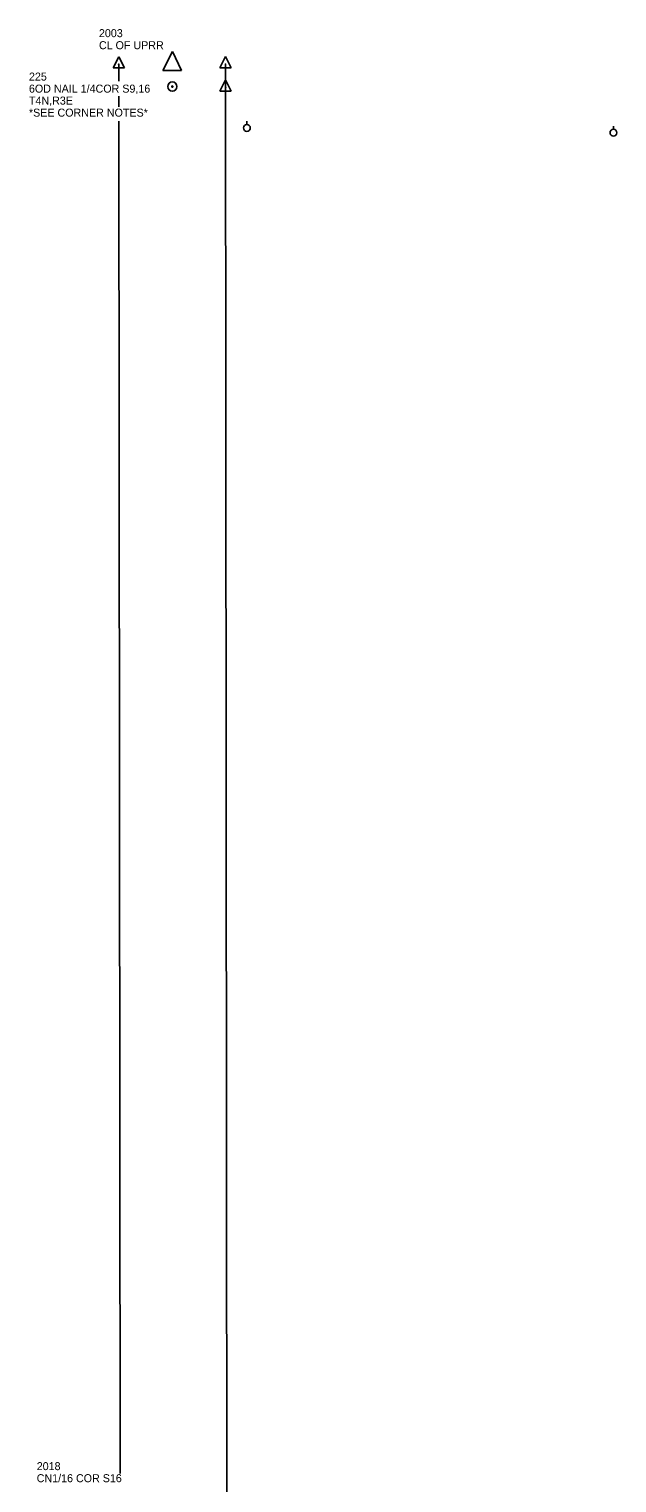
# Model space of a CAD drawing. Extents: x 1674300 to 1677561, y 225056 to 231852.
# Drawn here: x 1674554 to 1675105, y 230490 to 231852 of the extents above; entities that cross this region are included whole.
import ezdxf

# ---------------------------------------------------------------- set-up
doc = ezdxf.new("R2010")
doc.units = 0
for name, color, linetype in [('S_CAL_CORNER', 7, 'Continuous'), ('S_CAL_CORNER_ANNOT', 7, 'Continuous'), ('S_EXIST_ROW', 7, 'Continuous'), ('S_IRON_PIN', 7, 'Continuous'), ('S_IRON_PIN_ANNOT', 7, 'Continuous'), ('S_UTILITY_POLE', 7, 'Continuous')]:
    doc.layers.add(name, color=color, linetype=linetype)

msp = doc.modelspace()

# ---------------------------------------------------------------- linework, layer by layer
at = {"layer": 'S_CAL_CORNER'}
for p, q in [((1674688.7, 231831.5), (1674679.9, 231813.8)), ((1674688.7, 231831.5), (1674697.4, 231813.8)), ((1674679.9, 231813.8), (1674697.4, 231813.8))]:
    msp.add_line(p, q, dxfattribs=at)
at = {"layer": 'S_EXIST_ROW'}
for p, q in [((1674638.6, 231826.6), (1674633.3, 231816)), ((1674638.6, 231826.6), (1674643.8, 231816)), ((1674738.6, 231826.7), (1674733.3, 231816.1)), ((1674738.6, 231826.7), (1674743.8, 231816.1)), ((1674633.3, 231816), (1674643.8, 231816)), ((1674638.5, 231819.5), (1674638.5, 231819.5)), ((1674638.6, 231803.8), (1674638.5, 231819.5)), ((1674733.3, 231816.1), (1674743.8, 231816.1)), ((1674738.5, 231819.6), (1674738.5, 231819.6)), ((1674743.8, 226481.8), (1674738.5, 231819.6)), ((1674738.6, 231804.9), (1674733.3, 231794.3)), ((1674738.6, 231804.9), (1674743.8, 231794.3)), ((1674738.6, 231797.8), (1674738.6, 231797.8)), ((1674638.6, 231779.6), (1674638.6, 231789.7)), ((1674733.3, 231794.3), (1674743.8, 231794.3)), ((1674639.8, 230498.5), (1674638.6, 231766.3))]:
    msp.add_line(p, q, dxfattribs=at)
for centre, radius in [((1674638.5, 231819.5), 0.18), ((1674638.5, 231819.5), 0.09), ((1674738.5, 231819.6), 0.18), ((1674738.5, 231819.6), 0.09), ((1674738.6, 231797.8), 0.18), ((1674738.6, 231797.8), 0.09)]:
    msp.add_circle(centre, radius, dxfattribs=at)
at = {"layer": 'S_IRON_PIN'}
for radius in [4.36, 0.617, 0.392, 0.317, 0.218, 0.0872, 0.123]:
    msp.add_circle((1674688.7, 231798.6), radius, dxfattribs=at)
at = {"layer": 'S_UTILITY_POLE'}
for p, q in [((1674758.4, 231763), (1674758.4, 231766.2)), ((1675102.1, 231758.5), (1675102.1, 231761.6))]:
    msp.add_line(p, q, dxfattribs=at)
for centre in [(1674758.6, 231759.8), (1675102.2, 231755.3)]:
    msp.add_circle(centre, 3.19, dxfattribs=at)

# ---------------------------------------------------------------- texts
at = {"layer": 'S_CAL_CORNER_ANNOT'}
for s, p in [('2003', (1674619.9, 231844.9)), ('CL OF UPRR', (1674619.9, 231833.6)), ('2018', (1674561.6, 230501.5)), ('CN1/16 COR S16', (1674561.6, 230490.2))]:
    msp.add_text(s, height=7.5, dxfattribs=at).set_placement(p)
at = {"layer": 'S_IRON_PIN_ANNOT'}
for s, p in [('225', (1674554.3, 231804.2)), ('6OD NAIL 1/4COR S9,16', (1674554.3, 231792.9)), ('T4N,R3E', (1674554.3, 231781.7)), ('*SEE CORNER NOTES*', (1674554.3, 231770.4))]:
    msp.add_text(s, height=7.5, dxfattribs=at).set_placement(p)

doc.saveas('drawing.dxf')
